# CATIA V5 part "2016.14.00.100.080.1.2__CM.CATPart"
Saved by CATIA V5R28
Part number: 2016.14.00.100.080.1.2__CM
Property "id_number": "2016.14.00.100.080.1.2"
Publications: "Absolute Axis System", "driver", "slider", "base", "cam diagram"
Bounding box of the stored display mesh (mm): x -80 to 250, y -87.5 to 87.5, z 0 to 280
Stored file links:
  N:\B2\Normteile\K\2016\11-14\010\cm\2016.14.00.100.080.1.2__CM.CATPart
  H:\CAD_Startmodelle\Tests\fill-in_PRT-SL_TEMPLATE.xlsx
  H:\CAD_Startmodelle\V5-R24\R24_TEMPLATE_PRT_FIBRO_CAM_TECNOLOGIES_INDEX.xlsx
  H:\z_Einordnen\170511__Anfrage_TK_HN\170511__CC01_TKHN.CATPart
  N:\B2\Normteile\K\2016\9xxx\2016.9024.1705.001\Entwurf_\170511__CC01_TKHN.CATPart
  N:\B2\Normteile\K\2016\9xxx\2016.9024.1707.006\Konstruktion\2016.9024.1707.006__HP__CUSTOMIZED_CAM_CM.CATPart
  N:\B2\Normteile\K\2016\9xxx\2016.9024.1707.005\Konstruktion\2016.9024.1707.005__HP__CUSTOMIZED_CAM_CM.CATPart
  N:\B2\Normteile\K\2016\9xxx\2016.9024.1707.008\Konstruktion\2016.9024.1707.008__HP__CUSTOMIZED_CAM_CM.CATPart
  N:\B2\Normteile\K\2016\9xxx\2016.9024.1707.009\Konstruktion\2016.9024.1707.009__HP__CUSTOMIZED_CAM_CM.CATPart
  N:\B2\Normteile\K\2016\9xxx\2016.9024.1707.010\Konstruktion\2016.9024.1707.010__HP__CUSTOMIZED_CAM_CM.CATPart
  N:\B2\Normteile\K\2016\9xxx\2016.9024.1708.002\Konstruktion\2016.9024.1708.002__HP__CUSTOMIZED_CAM_CM.CATPart
  N:\B2\Normteile\K\2016\9xxx\2016.9024.1802.001\Konstruktion\2016.9024.1802.001__HP__CUSTOMIZED_CAM_CM.CATPart
  N:\B2\Normteile\K\2016\9xxx\2016.9024.1802.002\Konstruktion\2016.9024.1802.002__HP__CUSTOMIZED_CAM_CM.CATPart
  N:\B2\Normteile\K\2016\9xxx\2016.9024.1811.003\Konstruktion\2016.9024.1811.003__HP__CUSTOMIZED_CAM_CM.CATPart
  N:\B2\Normteile\K\2016\9xxx\2016.9015.1811.001\Konstruktion\am\2016.9015.1811.001__AM__FCC_HV_DMC_0125-00.CATPart
  N:\B2\Normteile\K\2016\9xxx\2016.9024.1811.009\Konstruktion\2016.9024.1811.009__HP__CUSTOMIZED_CAM_CM.CATPart
  N:\B2\Normteile\K\2016\9xxx\2016.9024.1911.002\Konstruktion\am\2016.9024.1911.002__AM__CUSTOMIZED_CAM_CM.CATPart
  N:\B2\Normteile\K\2016\9xxx\2016.9024.2002.006\Konstruktion\2016.9024.2002.006__AM.CATPart
  N:\B2\Normteile\K\2016\9xxx\2016.9024.2004.001\Konstruktion\2016.9024.2004.001__AM__FCC_HV_CAEC_0260-45.CATPart
  N:\B2\Normteile\K\2016\9xxx\2016.9024.2006.002\Konstruktion\2016.9024.2006.002__AM__FCC_HV_CAEC_0260-40.CATPart
  N:\B2\Normteile\K\2016\9xxx\2016.9024.2006.005\Konstruktion\am\2016.9024.2006.005__AM__CFCC_HV_AEPC_0080-65.CATPart
  N:\B2\Normteile\K\2016\9xxx\2016.9024.2006.004\Konstruktion\am\2016.9024.2006.004__AM__CFCC_HV_AEC_0210-35.CATPart
  N:\B2\Normteile\K\2016\9xxx\2016.9026.2006.001\Konstruktion\am\2016.9026.2006.001__AM__FCC_LV_CAEC_0180-40.CATPart
  N:\B2\Normteile\K\2016\9xxx\2016.9015.2007.001\Konstruktion\am\2016.9015.2007.001__AM__FCC_HV_CDMPC_0090-00.CATPart
  N:\B2\Normteile\K\2016\9xxx\2016.9024.2005.001\Konstruktion\am\2016.9024.2005.001__AM__CFCC_HV_AEPC_1400-70.CATPart
  N:\B2\Normteile\K\2016\9xxx\2016.9024.2007.004\Konstruktion\am\2016.9024.2007.004__AM__CFCC_HV_AEC_1250-80.CATPart
  N:\B2\Normteile\K\2016\11-14\005\2016.11.00.052.040.1.02__AS__DIE_MOUNT_CAM__W52_A0_S40.CATProduct
  N:\B2\Normteile\K\2016\11-14\cm\005\catia\2016.11.00.052.025.1.2__CM.CATPart
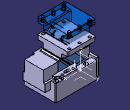
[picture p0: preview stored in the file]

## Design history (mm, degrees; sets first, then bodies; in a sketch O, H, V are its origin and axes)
Parameters
  group "process_parameters"
    modeltype = ""
    stocklist = ""
    id_number = "2016.14.00.100.080.1.2"
    id_number_rough_part = ""
    revision_index = ""
    revision_date = ""
    revision_description = ""
    category = ""
    material = ""
    manufacturing_information = ""
    standard = ""
  group "release_parameters_startmodel"
    sm_revision_index = "2016_00" {design table}
    sm_revision_date = "20.08.2016" {design table}
    sm_revision_name = "Meyer" {design table}
    sm_revision_description = "new part template FIBRO cam tecnologies" {design table}
AxisSystem1: origin (0, 0, 0), X (1, 0, 0), Y (0, 1, 0), Z (0, 0, 1)
Set1 "reference elements"
  Sketch1 "cam diagram" on ZX plane of AxisSystem1, origin (0, 0, 0), H (-1, 0, 0), V (0, 0, 1)
    line L1 (0, 0) -> (80, 0)
    line L2 (80, 0) -> (0, 80)
    point P2 (0, 80)
    line L3 (0, 80) -> (0, 0)
    length L1 = 80
    angle H L2 = 45
    horizontal: L1 H
    coincidence: P2 V
    vertical: L3 V
Body1 "finished_part" (main body)
  Body2 "rough_part"
  Add1 "rough_part": tool Body2
  Body3 "milling operations"
  Remove1 "milling operations": tool Body3
  Body4 "drilling operations"
  Remove2 "drilling operations": tool Body4
Body5 "driver"
  Solid1: solid without history
Body6 "slider"
  Solid2: solid without history
Body7 "base"
  Solid3: solid without history
Body8 "opened position"
  Body9 "slider"
    Body10 "slider"
      Solid4: linked copy from another document
    Assemble1: tool Body10
    Translate1: FirstPoint vertex [element of Sketch1 | element of Sketch1], SecondPoint vertex [element of Sketch1 | element of Sketch1], ToTransfor Assemble1
  Assemble2: tool Body9
  Body11 "driver"
    Body12 "driver"
      Solid5: linked copy from another document
    Assemble3: tool Body12
    Translate2: FirstPoint vertex [element of Sketch1 | element of Sketch1], SecondPoint vertex [element of Sketch1 | element of Sketch1], ToTransfor Assemble3
  Assemble4: tool Body11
